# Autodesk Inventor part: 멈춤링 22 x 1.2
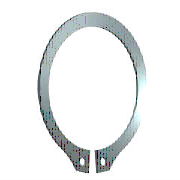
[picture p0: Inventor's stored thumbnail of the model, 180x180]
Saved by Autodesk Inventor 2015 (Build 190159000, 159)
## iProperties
IsCustomPart: 0
Created: 2009-02
Part Number: 멈춤링 22 x 1.2
Material: Steel, Mild
Description: 리테이닝 링(C형)
Document SubType Name: Modeling
Standard: KS B 1336
Designer: SeoGD™
Standards Organization: KS
Language: ko-KR
Size Designation: 22 x 1.2
Categories: <MemberInstance><Categories><Category DisplayName="샤프트 부품" InternalName="7f7aeb1f-a693-4053-b835-cee3144e0d98" Mnemonic="SHFT"><Category DisplayName="써클립" Inter
Density: 1 g/cm^3
Appearance: Metal-Steel
Author: SeoGD™
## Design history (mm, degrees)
sketch "스케치1"
  geometry: L1 (-6, 0)-(6, 0) reference; L2 (0, 20.189)-(0, -80.536) reference; L3 (-48.09, 0)-(48.09, 0) reference; L4 (-0.5, -21.488)-(-0.5, -25.588); L5 (-0.5, -6.54)-(-0.5, -13.29); L6 (-2.795, 2.7)-(3.672, 2.7); L7 (0.5, -6.54)-(0.5, -13.29); L8 (0.5, -21.488)-(0.5, -25.588); C1 r 1 at (-2, -23.437); C2 r 1 at (2, -23.437); A1 r 10.5 centre (0, -11) between (0.5, -21.488) and (-0.5, -21.488); A2 r 13.025 centre (0, -10.325) between (5.149, -22.289) and (-5.149, -22.289); A3 r 14.597 centre (0, -11) between (-2.318, -25.411) and (-0.5, -25.588); A4 r 2 centre (-2, -23.437) between (-3.97, -23.781) and (-2.318, -25.411); A5 r 2 centre (-5.94, -24.126) between (-3.97, -23.781) and (-5.149, -22.289); A6 r 2 centre (5.94, -24.126) between (5.149, -22.289) and (3.97, -23.781); A7 r 2 centre (2, -23.437) between (2.318, -25.411) and (3.97, -23.781); A8 r 14.597 centre (0, -11) between (0.5, -25.588) and (2.318, -25.411)
  constraints: 16 point on circle, 12 end point, 10 centre point, 9 symmetric about line, 5 point on line, 4 tangent, 3 coincident, 2 horizontal, 1 perpendicular, 1 vertical, 5 other
  dimensions: "d0" = 21 diameter of A1 (= ND); "d1" = 4.1 distance of L4.end L4.start (= SRB2); "d6" = 0.5 distance between parallel lines of L2 L5 (= 0.25 x SD5); "d7" = 2.7 distance between parallel lines of L6 L3 (= SRB1); "d8" = 0.675 distance of A1.centre A2.centre (= 0.25 x SRB1); "d9" = 2 radius of A4 (= SD5); "d10" = 2 radius of A5 (= SD5); "d11" = 1.5 distance from line of L4 A4.centre (= 0.75 x SD5); "d12" = 2 diameter of C1 (= SD5); "d13" = 2 diameter of C2 (= SD5); "d14" = 11 distance from line of A1.centre L1 (= 0.5 x WD)
extrude "본체" new body sketch "스케치1" distance "d2" = 1.2 (= SD); taper "d3" = 0 deg
workaxis "Work Axis1"
workplane "Work Plane1"
body "Solid1"
other parameters: "WD" = 22 (= WDMIN) [user parameter; used in 1 equation term], "SD" = 1.2 [user parameter; used in 1 equation term], "SRB1" = 2.7 [user parameter; used in 2 equation terms], "ND" = 21 [user parameter; used in 1 equation term], "SRB2" = 4.1 [user parameter; used in 1 equation term], "SD5" = 2 [user parameter; used in 6 equation terms], "d15" = 0, "d16" = 0, "d17" = 0, "d41" = 0, "d42" = 0, "WDMIN" = 22 [user parameter; used in 1 equation term], "SD3" = 20.5 [user parameter], "WDMAX" = 24 [user parameter]
